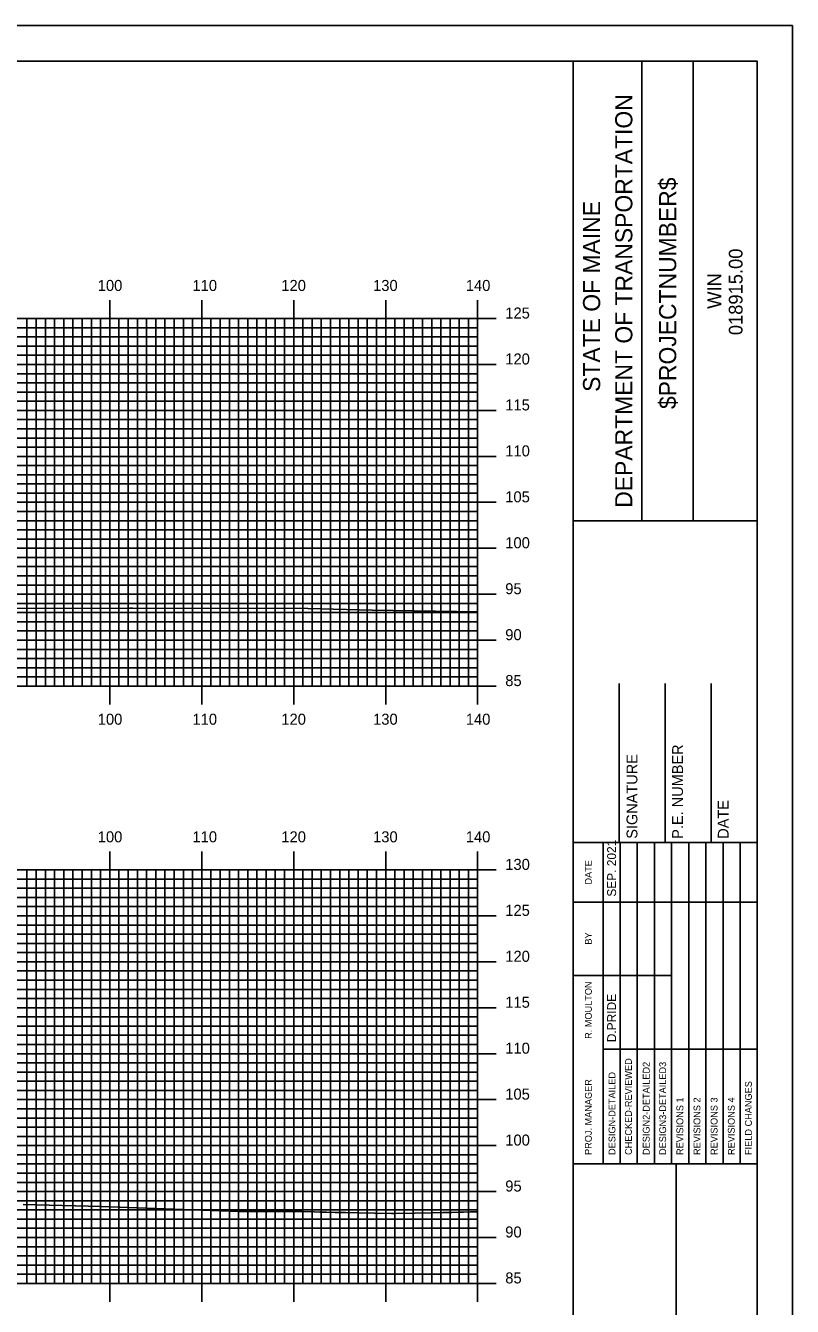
# Model space of a CAD drawing. Extents: x 1786189 to 1786532, y 442591 to 442811.
# Drawn here: x 1786445.4 to 1786528.8, y 442671.2 to 442810.5 of the extents above; entities that cross this region are included whole.
import ezdxf

# ---------------------------------------------------------------- set-up
doc = ezdxf.new("R2010")
doc.units = 0
for name, color, linetype in [('BORDER', 7, 'Continuous'), ('H_V ANNOTATION', 7, 'Continuous'), ('MAJOR', 7, 'Continuous'), ('MINOR', 7, 'Continuous'), ('PLOT BOUNDARY', 7, 'Continuous'), ('S_Roadway_Centerline', 7, 'Continuous')]:
    doc.layers.add(name, color=color, linetype=linetype)

msp = doc.modelspace()

# ---------------------------------------------------------------- linework, layer by layer
at = {"layer": 'BORDER'}
for p, q in [((1786504.96, 442596.67), (1786504.96, 442806.67)), ((1786512.42, 442756.66), (1786512.42, 442806.66)), ((1786518.01, 442756.66), (1786518.01, 442806.66)), ((1786504.97, 442756.65), (1786524.96, 442756.65)), ((1786509.96, 442721.67), (1786509.96, 442738.97)), ((1786514.96, 442721.67), (1786514.96, 442738.97)), ((1786519.96, 442721.67), (1786519.96, 442738.97)), ((1786504.96, 442721.67), (1786524.96, 442721.67)), ((1786504.96, 442686.67), (1786524.96, 442686.67)), ((1786516.15, 442616.67), (1786516.15, 442686.67))]:
    msp.add_line(p, q, dxfattribs=at)
msp.add_lwpolyline([(1786204.96, 442596.67), (1786524.96, 442596.67), (1786524.96, 442806.67), (1786204.96, 442806.67)], close=True, dxfattribs=at)
for points in [[(1786508.19, 442715.17), (1786508.19, 442721.67)], [(1786510.06, 442686.68), (1786510.06, 442721.67)], [(1786511.92, 442721.67), (1786511.92, 442686.68)], [(1786513.79, 442686.68), (1786513.79, 442721.67)], [(1786515.65, 442686.68), (1786515.65, 442721.67)], [(1786517.51, 442686.68), (1786517.51, 442721.67)], [(1786519.38, 442686.68), (1786519.38, 442721.67)], [(1786521.24, 442686.68), (1786521.24, 442721.67)], [(1786523.1, 442686.68), (1786523.1, 442721.67)], [(1786508.2, 442686.68), (1786508.2, 442720.26)], [(1786504.96, 442715.17), (1786524.96, 442715.17)], [(1786504.96, 442707.17), (1786508.2, 442707.17)], [(1786508.19, 442707.17), (1786515.65, 442707.17)], [(1786508.19, 442699.17), (1786524.96, 442699.17)]]:
    msp.add_lwpolyline(points, dxfattribs=at)
at = {"layer": 'MAJOR'}
for p, q in [((1786454.56, 442780.67), (1786454.56, 442778.67)), ((1786464.56, 442780.67), (1786464.56, 442778.67)), ((1786474.56, 442780.67), (1786474.56, 442778.67)), ((1786484.56, 442780.67), (1786484.56, 442778.67)), ((1786494.56, 442780.67), (1786494.56, 442778.67)), ((1786214.56, 442778.67), (1786494.56, 442778.67)), ((1786214.56, 442778.67), (1786494.56, 442778.67)), ((1786454.56, 442738.67), (1786454.56, 442778.67)), ((1786464.56, 442738.67), (1786464.56, 442778.67)), ((1786474.56, 442738.67), (1786474.56, 442778.67)), ((1786484.56, 442738.67), (1786484.56, 442778.67)), ((1786496.57, 442778.67), (1786492.56, 442778.67)), ((1786494.56, 442738.67), (1786494.56, 442778.67)), ((1786494.56, 442738.67), (1786494.56, 442778.67)), ((1786214.56, 442773.67), (1786494.56, 442773.67)), ((1786496.57, 442773.67), (1786492.56, 442773.67)), ((1786214.56, 442768.67), (1786494.56, 442768.67)), ((1786496.57, 442768.67), (1786492.56, 442768.67)), ((1786214.56, 442763.67), (1786494.56, 442763.67)), ((1786496.57, 442763.67), (1786492.56, 442763.67)), ((1786214.56, 442758.67), (1786494.56, 442758.67)), ((1786496.57, 442758.67), (1786492.56, 442758.67)), ((1786214.56, 442753.67), (1786494.56, 442753.67)), ((1786496.57, 442753.67), (1786492.56, 442753.67)), ((1786214.56, 442748.67), (1786494.56, 442748.67)), ((1786496.57, 442748.67), (1786492.56, 442748.67)), ((1786214.56, 442743.67), (1786494.56, 442743.67)), ((1786496.57, 442743.67), (1786492.56, 442743.67)), ((1786214.56, 442738.67), (1786494.56, 442738.67)), ((1786214.56, 442738.67), (1786494.56, 442738.67)), ((1786454.56, 442736.66), (1786454.56, 442738.67)), ((1786464.56, 442736.66), (1786464.56, 442738.67)), ((1786474.56, 442736.66), (1786474.56, 442738.67)), ((1786484.56, 442736.66), (1786484.56, 442738.67)), ((1786496.57, 442738.67), (1786492.56, 442738.67)), ((1786494.56, 442736.66), (1786494.56, 442738.67)), ((1786454.56, 442720.67), (1786454.56, 442718.67)), ((1786464.56, 442720.67), (1786464.56, 442718.67)), ((1786474.56, 442720.67), (1786474.56, 442718.67)), ((1786484.56, 442720.67), (1786484.56, 442718.67)), ((1786494.56, 442720.67), (1786494.56, 442718.67)), ((1786214.56, 442718.67), (1786494.56, 442718.67)), ((1786214.56, 442718.67), (1786494.56, 442718.67)), ((1786454.56, 442673.67), (1786454.56, 442718.67)), ((1786464.56, 442673.67), (1786464.56, 442718.67)), ((1786474.56, 442673.67), (1786474.56, 442718.67)), ((1786484.56, 442673.67), (1786484.56, 442718.67)), ((1786496.57, 442718.67), (1786492.56, 442718.67)), ((1786494.56, 442673.67), (1786494.56, 442718.67)), ((1786494.56, 442673.67), (1786494.56, 442718.67)), ((1786214.56, 442713.67), (1786494.56, 442713.67)), ((1786496.57, 442713.67), (1786492.56, 442713.67)), ((1786214.56, 442708.67), (1786494.56, 442708.67)), ((1786496.57, 442708.67), (1786492.56, 442708.67)), ((1786214.56, 442703.67), (1786494.56, 442703.67)), ((1786496.57, 442703.67), (1786492.56, 442703.67)), ((1786214.56, 442698.67), (1786494.56, 442698.67)), ((1786496.57, 442698.67), (1786492.56, 442698.67)), ((1786214.56, 442693.67), (1786494.56, 442693.67)), ((1786496.57, 442693.67), (1786492.56, 442693.67)), ((1786214.56, 442688.67), (1786494.56, 442688.67)), ((1786496.57, 442688.67), (1786492.56, 442688.67)), ((1786214.56, 442683.67), (1786494.56, 442683.67)), ((1786496.57, 442683.67), (1786492.56, 442683.67)), ((1786214.56, 442678.67), (1786494.56, 442678.67)), ((1786496.57, 442678.67), (1786492.56, 442678.67)), ((1786214.56, 442673.67), (1786494.56, 442673.67)), ((1786214.56, 442673.67), (1786494.56, 442673.67)), ((1786454.56, 442671.66), (1786454.56, 442673.67)), ((1786464.56, 442671.66), (1786464.56, 442673.67)), ((1786474.56, 442671.66), (1786474.56, 442673.67)), ((1786484.56, 442671.66), (1786484.56, 442673.67)), ((1786496.57, 442673.67), (1786492.56, 442673.67)), ((1786494.56, 442671.66), (1786494.56, 442673.67))]:
    msp.add_line(p, q, dxfattribs=at)
at = {"layer": 'MINOR'}
for p, q in [((1786445.56, 442738.67), (1786445.56, 442778.67)), ((1786446.56, 442738.67), (1786446.56, 442778.67)), ((1786447.56, 442738.67), (1786447.56, 442778.67)), ((1786448.56, 442738.67), (1786448.56, 442778.67)), ((1786449.56, 442738.67), (1786449.56, 442778.67)), ((1786450.56, 442738.67), (1786450.56, 442778.67)), ((1786451.56, 442738.67), (1786451.56, 442778.67)), ((1786452.56, 442738.67), (1786452.56, 442778.67)), ((1786453.56, 442738.67), (1786453.56, 442778.67)), ((1786455.56, 442738.67), (1786455.56, 442778.67)), ((1786456.56, 442738.67), (1786456.56, 442778.67)), ((1786457.56, 442738.67), (1786457.56, 442778.67)), ((1786458.56, 442738.67), (1786458.56, 442778.67)), ((1786459.56, 442738.67), (1786459.56, 442778.67)), ((1786460.56, 442738.67), (1786460.56, 442778.67)), ((1786461.56, 442738.67), (1786461.56, 442778.67)), ((1786462.56, 442738.67), (1786462.56, 442778.67)), ((1786463.56, 442738.67), (1786463.56, 442778.67)), ((1786465.56, 442738.67), (1786465.56, 442778.67)), ((1786466.56, 442738.67), (1786466.56, 442778.67)), ((1786467.56, 442738.67), (1786467.56, 442778.67)), ((1786468.56, 442738.67), (1786468.56, 442778.67)), ((1786469.56, 442738.67), (1786469.56, 442778.67)), ((1786470.56, 442738.67), (1786470.56, 442778.67)), ((1786471.56, 442738.67), (1786471.56, 442778.67)), ((1786472.56, 442738.67), (1786472.56, 442778.67)), ((1786473.56, 442738.67), (1786473.56, 442778.67)), ((1786475.56, 442738.67), (1786475.56, 442778.67)), ((1786476.56, 442738.67), (1786476.56, 442778.67)), ((1786477.56, 442738.67), (1786477.56, 442778.67)), ((1786478.56, 442738.67), (1786478.56, 442778.67)), ((1786479.56, 442738.67), (1786479.56, 442778.67)), ((1786480.56, 442738.67), (1786480.56, 442778.67)), ((1786481.56, 442738.67), (1786481.56, 442778.67)), ((1786482.56, 442738.67), (1786482.56, 442778.67)), ((1786483.56, 442738.67), (1786483.56, 442778.67)), ((1786485.56, 442738.67), (1786485.56, 442778.67)), ((1786486.56, 442738.67), (1786486.56, 442778.67)), ((1786487.56, 442738.67), (1786487.56, 442778.67)), ((1786488.56, 442738.67), (1786488.56, 442778.67)), ((1786489.56, 442738.67), (1786489.56, 442778.67)), ((1786490.56, 442738.67), (1786490.56, 442778.67)), ((1786491.56, 442738.67), (1786491.56, 442778.67)), ((1786492.56, 442738.67), (1786492.56, 442778.67)), ((1786493.56, 442738.67), (1786493.56, 442778.67)), ((1786214.56, 442777.67), (1786494.56, 442777.67)), ((1786494.56, 442777.67), (1786492.56, 442777.67)), ((1786214.56, 442776.67), (1786494.56, 442776.67)), ((1786214.56, 442775.67), (1786494.56, 442775.67)), ((1786494.56, 442776.67), (1786492.56, 442776.67)), ((1786494.56, 442775.67), (1786492.56, 442775.67)), ((1786214.56, 442774.67), (1786494.56, 442774.67)), ((1786494.56, 442774.67), (1786492.56, 442774.67)), ((1786214.56, 442772.67), (1786494.56, 442772.67)), ((1786214.56, 442771.67), (1786494.56, 442771.67)), ((1786494.56, 442772.67), (1786492.56, 442772.67)), ((1786494.56, 442771.67), (1786492.56, 442771.67)), ((1786214.56, 442770.67), (1786494.56, 442770.67)), ((1786494.56, 442770.67), (1786492.56, 442770.67)), ((1786214.56, 442769.67), (1786494.56, 442769.67)), ((1786494.56, 442769.67), (1786492.56, 442769.67)), ((1786214.56, 442767.67), (1786494.56, 442767.67)), ((1786494.56, 442767.67), (1786492.56, 442767.67)), ((1786214.56, 442766.67), (1786494.56, 442766.67)), ((1786494.56, 442766.67), (1786492.56, 442766.67)), ((1786214.56, 442765.67), (1786494.56, 442765.67)), ((1786214.56, 442764.67), (1786494.56, 442764.67)), ((1786494.56, 442765.67), (1786492.56, 442765.67)), ((1786494.56, 442764.67), (1786492.56, 442764.67)), ((1786214.56, 442762.67), (1786494.56, 442762.67)), ((1786214.56, 442761.67), (1786494.56, 442761.67)), ((1786494.56, 442762.67), (1786492.56, 442762.67)), ((1786494.56, 442761.67), (1786492.56, 442761.67)), ((1786214.56, 442760.67), (1786494.56, 442760.67)), ((1786494.56, 442760.67), (1786492.56, 442760.67)), ((1786214.56, 442759.67), (1786494.56, 442759.67)), ((1786494.56, 442759.67), (1786492.56, 442759.67)), ((1786214.56, 442757.67), (1786494.56, 442757.67)), ((1786494.56, 442757.67), (1786492.56, 442757.67)), ((1786214.56, 442756.67), (1786494.56, 442756.67)), ((1786494.56, 442756.67), (1786492.56, 442756.67)), ((1786214.56, 442755.67), (1786494.56, 442755.67)), ((1786214.56, 442754.67), (1786494.56, 442754.67)), ((1786494.56, 442755.67), (1786492.56, 442755.67)), ((1786494.56, 442754.67), (1786492.56, 442754.67)), ((1786214.56, 442752.67), (1786494.56, 442752.67)), ((1786494.56, 442752.67), (1786492.56, 442752.67)), ((1786214.56, 442751.67), (1786494.56, 442751.67)), ((1786214.56, 442750.67), (1786494.56, 442750.67)), ((1786494.56, 442751.67), (1786492.56, 442751.67)), ((1786494.56, 442750.67), (1786492.56, 442750.67)), ((1786214.56, 442749.67), (1786494.56, 442749.67)), ((1786494.56, 442749.67), (1786492.56, 442749.67)), ((1786214.56, 442747.67), (1786494.56, 442747.67)), ((1786494.56, 442747.67), (1786492.56, 442747.67)), ((1786214.56, 442746.67), (1786494.56, 442746.67)), ((1786494.56, 442746.67), (1786492.56, 442746.67)), ((1786214.56, 442745.67), (1786494.56, 442745.67)), ((1786494.56, 442745.67), (1786492.56, 442745.67)), ((1786214.56, 442744.67), (1786494.56, 442744.67)), ((1786494.56, 442744.67), (1786492.56, 442744.67)), ((1786214.56, 442742.67), (1786494.56, 442742.67)), ((1786494.56, 442742.67), (1786492.56, 442742.67)), ((1786214.56, 442741.67), (1786494.56, 442741.67)), ((1786494.56, 442741.67), (1786492.56, 442741.67)), ((1786214.56, 442740.67), (1786494.56, 442740.67)), ((1786214.56, 442739.67), (1786494.56, 442739.67)), ((1786494.56, 442740.67), (1786492.56, 442740.67)), ((1786494.56, 442739.67), (1786492.56, 442739.67)), ((1786445.56, 442673.67), (1786445.56, 442718.67)), ((1786446.56, 442673.67), (1786446.56, 442718.67)), ((1786447.56, 442673.67), (1786447.56, 442718.67)), ((1786448.56, 442673.67), (1786448.56, 442718.67)), ((1786449.56, 442673.67), (1786449.56, 442718.67)), ((1786450.56, 442673.67), (1786450.56, 442718.67)), ((1786451.56, 442673.67), (1786451.56, 442718.67)), ((1786452.56, 442673.67), (1786452.56, 442718.67)), ((1786453.56, 442673.67), (1786453.56, 442718.67)), ((1786455.56, 442673.67), (1786455.56, 442718.67)), ((1786456.56, 442673.67), (1786456.56, 442718.67)), ((1786457.56, 442673.67), (1786457.56, 442718.67)), ((1786458.56, 442673.67), (1786458.56, 442718.67)), ((1786459.56, 442673.67), (1786459.56, 442718.67)), ((1786460.56, 442673.67), (1786460.56, 442718.67)), ((1786461.56, 442673.67), (1786461.56, 442718.67)), ((1786462.56, 442673.67), (1786462.56, 442718.67)), ((1786463.56, 442673.67), (1786463.56, 442718.67)), ((1786465.56, 442673.67), (1786465.56, 442718.67)), ((1786466.56, 442673.67), (1786466.56, 442718.67)), ((1786467.56, 442673.67), (1786467.56, 442718.67)), ((1786468.56, 442673.67), (1786468.56, 442718.67)), ((1786469.56, 442673.67), (1786469.56, 442718.67)), ((1786470.56, 442673.67), (1786470.56, 442718.67)), ((1786471.56, 442673.67), (1786471.56, 442718.67)), ((1786472.56, 442673.67), (1786472.56, 442718.67)), ((1786473.56, 442673.67), (1786473.56, 442718.67)), ((1786475.56, 442673.67), (1786475.56, 442718.67)), ((1786476.56, 442673.67), (1786476.56, 442718.67)), ((1786477.56, 442673.67), (1786477.56, 442718.67)), ((1786478.56, 442673.67), (1786478.56, 442718.67)), ((1786479.56, 442673.67), (1786479.56, 442718.67)), ((1786480.56, 442673.67), (1786480.56, 442718.67)), ((1786481.56, 442673.67), (1786481.56, 442718.67)), ((1786482.56, 442673.67), (1786482.56, 442718.67)), ((1786483.56, 442673.67), (1786483.56, 442718.67)), ((1786485.56, 442673.67), (1786485.56, 442718.67)), ((1786486.56, 442673.67), (1786486.56, 442718.67)), ((1786487.56, 442673.67), (1786487.56, 442718.67)), ((1786488.56, 442673.67), (1786488.56, 442718.67)), ((1786489.56, 442673.67), (1786489.56, 442718.67)), ((1786490.56, 442673.67), (1786490.56, 442718.67)), ((1786491.56, 442673.67), (1786491.56, 442718.67)), ((1786492.56, 442673.67), (1786492.56, 442718.67)), ((1786493.56, 442673.67), (1786493.56, 442718.67)), ((1786214.56, 442717.67), (1786494.56, 442717.67)), ((1786494.56, 442717.67), (1786492.56, 442717.67)), ((1786214.56, 442716.67), (1786494.56, 442716.67)), ((1786214.56, 442715.67), (1786494.56, 442715.67)), ((1786494.56, 442716.67), (1786492.56, 442716.67)), ((1786494.56, 442715.67), (1786492.56, 442715.67)), ((1786214.56, 442714.67), (1786494.56, 442714.67)), ((1786494.56, 442714.67), (1786492.56, 442714.67)), ((1786214.56, 442712.67), (1786494.56, 442712.67)), ((1786214.56, 442711.67), (1786494.56, 442711.67)), ((1786494.56, 442712.67), (1786492.56, 442712.67)), ((1786494.56, 442711.67), (1786492.56, 442711.67)), ((1786214.56, 442710.67), (1786494.56, 442710.67)), ((1786494.56, 442710.67), (1786492.56, 442710.67)), ((1786214.56, 442709.67), (1786494.56, 442709.67)), ((1786494.56, 442709.67), (1786492.56, 442709.67)), ((1786214.56, 442707.67), (1786494.56, 442707.67)), ((1786494.56, 442707.67), (1786492.56, 442707.67)), ((1786214.56, 442706.67), (1786494.56, 442706.67)), ((1786494.56, 442706.67), (1786492.56, 442706.67)), ((1786214.56, 442705.67), (1786494.56, 442705.67)), ((1786214.56, 442704.67), (1786494.56, 442704.67)), ((1786494.56, 442705.67), (1786492.56, 442705.67)), ((1786494.56, 442704.67), (1786492.56, 442704.67)), ((1786214.56, 442702.67), (1786494.56, 442702.67)), ((1786214.56, 442701.67), (1786494.56, 442701.67)), ((1786494.56, 442702.67), (1786492.56, 442702.67)), ((1786494.56, 442701.67), (1786492.56, 442701.67)), ((1786214.56, 442700.67), (1786494.56, 442700.67)), ((1786494.56, 442700.67), (1786492.56, 442700.67)), ((1786214.56, 442699.67), (1786494.56, 442699.67)), ((1786494.56, 442699.67), (1786492.56, 442699.67)), ((1786214.56, 442697.67), (1786494.56, 442697.67)), ((1786494.56, 442697.67), (1786492.56, 442697.67)), ((1786214.56, 442696.67), (1786494.56, 442696.67)), ((1786494.56, 442696.67), (1786492.56, 442696.67)), ((1786214.56, 442695.67), (1786494.56, 442695.67)), ((1786494.56, 442695.67), (1786492.56, 442695.67)), ((1786214.56, 442694.67), (1786494.56, 442694.67)), ((1786494.56, 442694.67), (1786492.56, 442694.67)), ((1786214.56, 442692.67), (1786494.56, 442692.67)), ((1786494.56, 442692.67), (1786492.56, 442692.67)), ((1786214.56, 442691.67), (1786494.56, 442691.67)), ((1786214.56, 442690.67), (1786494.56, 442690.67)), ((1786494.56, 442691.67), (1786492.56, 442691.67)), ((1786494.56, 442690.67), (1786492.56, 442690.67)), ((1786214.56, 442689.67), (1786494.56, 442689.67)), ((1786494.56, 442689.67), (1786492.56, 442689.67)), ((1786214.56, 442687.67), (1786494.56, 442687.67)), ((1786214.56, 442686.67), (1786494.56, 442686.67)), ((1786494.56, 442687.67), (1786492.56, 442687.67)), ((1786494.56, 442686.67), (1786492.56, 442686.67)), ((1786214.56, 442685.67), (1786494.56, 442685.67)), ((1786494.56, 442685.67), (1786492.56, 442685.67)), ((1786214.56, 442684.67), (1786494.56, 442684.67)), ((1786494.56, 442684.67), (1786492.56, 442684.67)), ((1786214.56, 442682.67), (1786494.56, 442682.67)), ((1786494.56, 442682.67), (1786492.56, 442682.67)), ((1786214.56, 442681.67), (1786494.56, 442681.67)), ((1786494.56, 442681.67), (1786492.56, 442681.67)), ((1786214.56, 442680.67), (1786494.56, 442680.67)), ((1786214.56, 442679.67), (1786494.56, 442679.67)), ((1786494.56, 442680.67), (1786492.56, 442680.67)), ((1786494.56, 442679.67), (1786492.56, 442679.67)), ((1786214.56, 442677.67), (1786494.56, 442677.67)), ((1786214.56, 442676.67), (1786494.56, 442676.67)), ((1786494.56, 442677.67), (1786492.56, 442677.67)), ((1786494.56, 442676.67), (1786492.56, 442676.67)), ((1786214.56, 442675.67), (1786494.56, 442675.67)), ((1786494.56, 442675.67), (1786492.56, 442675.67)), ((1786214.56, 442674.67), (1786494.56, 442674.67)), ((1786494.56, 442674.67), (1786492.56, 442674.67))]:
    msp.add_line(p, q, dxfattribs=at)
at = {"layer": 'PLOT BOUNDARY'}
msp.add_lwpolyline([(1786188.78, 442590.55), (1786528.78, 442590.55), (1786528.78, 442810.55), (1786188.78, 442810.55)], close=True, dxfattribs=at)
at = {"layer": 'S_Roadway_Centerline'}
for points in [[(1786315.33, 442748.76), (1786319.67, 442748.52), (1786327.56, 442748.26), (1786332.67, 442748.02), (1786346.24, 442748.03), (1786350.33, 442748.23), (1786353.55, 442747.97), (1786366.51, 442747.38), (1786374.73, 442747.46), (1786386.06, 442747.95), (1786395.41, 442748.05), (1786407.03, 442747.81), (1786414.01, 442747.51), (1786420.12, 442747.28), (1786428.37, 442747.04), (1786432.42, 442746.93), (1786435.54, 442747.12), (1786456.69, 442747.17), (1786456.78, 442747.16), (1786457.05, 442747.16), (1786476.09, 442747.11), (1786483.1, 442746.93), (1786494.56, 442746.74)], [(1786445.16, 442682.25), (1786453.66, 442682.05), (1786468.52, 442681.5), (1786474.1, 442681.51), (1786474.39, 442681.51), (1786474.72, 442681.5), (1786475.08, 442681.5), (1786475.3, 442681.49), (1786475.58, 442681.49), (1786476.8, 442681.46), (1786477.4, 442681.44), (1786478.14, 442681.42), (1786479.05, 442681.4), (1786480.19, 442681.38), (1786481.6, 442681.35), (1786483.35, 442681.31), (1786485.19, 442681.28), (1786485.56, 442681.28), (1786487.71, 442681.32), (1786489.51, 442681.35), (1786490.79, 442681.38), (1786491.74, 442681.4), (1786492.45, 442681.42), (1786493.01, 442681.43), (1786493.79, 442681.45), (1786494.07, 442681.45), (1786494.29, 442681.46), (1786494.39, 442681.46), (1786494.49, 442681.46), (1786494.56, 442681.46)]]:
    msp.add_lwpolyline(points, dxfattribs=at)

# ---------------------------------------------------------------- texts
at = {"layer": 'BORDER'}
for s, height, p in [('DEPARTMENT OF TRANSPORTATION', 1.8635, (1786511.38, 442758.08)), ('$PROJECTNUMBER$', 1.8635, (1786516.15, 442768.82)), ('STATE OF MAINE', 1.8635, (1786507.88, 442770.69)), ('018915.00', 1.491, (1786523.36, 442776.86)), ('WIN', 1.491, (1786521.04, 442779.73)), ('SIGNATURE', 1.181, (1786511.93, 442722.06)), ('P.E. NUMBER', 1.1811, (1786516.89, 442722.06)), ('DATE', 1.181, (1786521.85, 442722.06)), ('SEP. 2021', 0.969, (1786509.61, 442715.76)), ('DATE', 0.743, (1786506.97, 442717.08)), ('BY', 0.743, (1786506.97, 442710.54)), ('R. MOULTON', 0.745, (1786506.97, 442700.28)), ('D.PRIDE', 0.969, (1786509.61, 442699.92)), ('CHECKED-REVIEWED', 0.7455, (1786511.33, 442687.65)), ('DESIGN2-DETAILED2', 0.7455, (1786513.26, 442687.65)), ('DESIGN3-DETAILED3', 0.7455, (1786515.05, 442687.65)), ('DESIGN-DETAILED', 0.7455, (1786509.54, 442687.65)), ('PROJ. MANAGER', 0.7455, (1786506.97, 442687.65)), ('FIELD CHANGES', 0.7455, (1786524.37, 442687.65)), ('REVISIONS 1', 0.7455, (1786516.92, 442687.65)), ('REVISIONS 2', 0.7455, (1786518.78, 442687.65)), ('REVISIONS 3', 0.7455, (1786520.64, 442687.65)), ('REVISIONS 4', 0.7455, (1786522.51, 442687.65))]:
    msp.add_text(s, height=height, rotation=90, dxfattribs=at).set_placement(p)
at = {"layer": 'H_V ANNOTATION'}
for s, p in [('100', (1786453.25, 442781.67)), ('110', (1786463.55, 442781.67)), ('120', (1786473.21, 442781.67)), ('130', (1786483.19, 442781.67)), ('140', (1786493.27, 442781.67)), ('125', (1786497.56, 442778.67)), ('120', (1786497.56, 442773.67)), ('115', (1786497.56, 442768.67)), ('110', (1786497.56, 442763.67)), ('105', (1786497.56, 442758.67)), ('100', (1786497.56, 442753.67)), ('95', (1786497.56, 442748.67)), ('90', (1786497.56, 442743.67)), ('85', (1786497.56, 442738.67)), ('100', (1786453.25, 442734.47)), ('110', (1786463.55, 442734.47)), ('120', (1786473.21, 442734.47)), ('130', (1786483.19, 442734.47)), ('140', (1786493.27, 442734.47)), ('100', (1786453.25, 442721.67)), ('110', (1786463.55, 442721.67)), ('120', (1786473.21, 442721.67)), ('130', (1786483.19, 442721.67)), ('140', (1786493.27, 442721.67)), ('130', (1786497.56, 442718.67)), ('125', (1786497.56, 442713.67)), ('120', (1786497.56, 442708.67)), ('115', (1786497.56, 442703.67)), ('110', (1786497.56, 442698.67)), ('105', (1786497.56, 442693.67)), ('100', (1786497.56, 442688.67)), ('95', (1786497.56, 442683.67)), ('90', (1786497.56, 442678.67)), ('85', (1786497.56, 442673.67))]:
    msp.add_text(s, height=1.2, dxfattribs=at).set_placement(p)

doc.saveas('drawing.dxf')
